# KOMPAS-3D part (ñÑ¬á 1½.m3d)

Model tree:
1. Эскиз:1
2. Операция выдавливания:1
     Расстояние 1 = 0.6
3. Эскиз:2
4. Вырезать элемент выдавливания:1
     Толщина стенки 1 = 3; Толщина стенки 2 = 3; Расстояние 1 = 10
5. Эскиз:3
6. Вырезать элемент выдавливания:2
     Толщина стенки 1 = 3; Толщина стенки 2 = 3; Расстояние 1 = 10
7. Эскиз:4
8. Вырезать элемент выдавливания:3
     Толщина стенки 1 = 3; Толщина стенки 2 = 3; Расстояние 1 = 10
9. Эскиз:5
10. Вырезать элемент выдавливания:4
     Толщина стенки 1 = 3; Толщина стенки 2 = 3; Расстояние 1 = 10
11. Эскиз:6
12. Вырезать элемент выдавливания:5
     Расстояние 1 = 10
